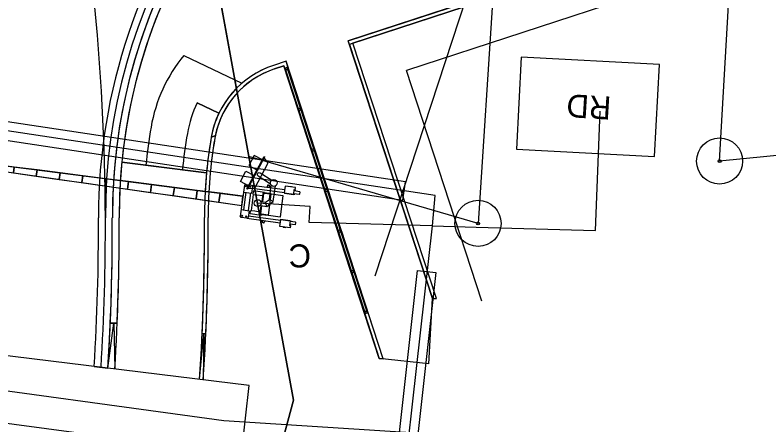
# Model space of a CAD drawing. Extents: x -728802 to -728097, y -1073200 to -1072700.
# Drawn here: x -728503.88 to -728487.53, y -1073043.74 to -1073034.86 of the extents above; entities that cross this region are included whole.
import ezdxf

# ---------------------------------------------------------------- set-up
doc = ezdxf.new("R2010")
doc.units = 0
for name, color, linetype in [('A5_JŽM', 7, 'Continuous'), ('Default', 7, 'Continuous'), ('Hranice parcel', 7, 'Continuous'), ('Projekt', 7, 'Continuous'), ('ZZZ_popisky', 7, 'Continuous')]:
    doc.layers.add(name, color=color, linetype=linetype)

# ---------------------------------------------------------------- blocks, each defined once
blk = doc.blocks.new('Závora C_2')
at = {"layer": 'Default'}
for p, q in [((-0.262, 0.267), (0.015, 1.015)), ((-0.033, 0.659), (0.235, 0.532)), ((-0.312, 0.367), (-0.338, 0.343)), ((-0.338, 0.343), (-0.338, -0.335)), ((-0.312, 0.367), (-0.189, 0.367)), ((-0.189, 0.367), (0.541, 0.367)), ((-0.189, 0.367), (-0.163, 0.343)), ((0.614, 0.452), (0.676, 0.452)), ((0.676, 0.452), (0.676, 0.445)), ((0.769, 0.395), (0.769, 0.367)), ((-0.338, 0.197), (-0.163, 0.197)), ((-0.288, 0.197), (-0.288, -0.188)), ((-0.187, 0.197), (-0.187, -0.188)), ((-0.163, 0.306), (0.541, 0.306)), ((-0.123, 0.174), (-0.123, -0.176)), ((0.259, 0.227), (0.259, -0.239)), ((-6.838, 0.058), (-0.338, 0.104)), ((-6.838, -0.049), (-6.838, 0.058)), ((-0.338, -0.096), (-0.338, 0.104)), ((-0.338, -0.096), (-0.338, 0.104)), ((-0.338, -0.096), (-0.338, 0.104)), ((-0.338, -0.096), (-0.338, 0.104)), ((0.202, -0.045), (0.165, 0.044)), ((0.329, 0.076), (0.239, 0.114)), ((-6.838, -0.049), (-0.338, -0.096)), ((-0.338, -0.188), (-0.163, -0.188)), ((-0.163, -0.188), (-0.163, -0.335)), ((-0.163, -0.298), (0.542, -0.298)), ((-0.312, -0.358), (-0.338, -0.335)), ((-0.189, -0.358), (-0.163, -0.335)), ((-0.189, -0.358), (0.542, -0.358)), ((0.614, -0.443), (0.676, -0.443)), ((0.676, -0.443), (0.676, -0.437)), ((0.769, -0.387), (0.769, -0.358))]:
    blk.add_line(p, q, dxfattribs=at)
for points in [[(-0.025, 0.945), (-0.214, 1.015), (-0.301, 0.78), (-0.112, 0.71)], [(-0.262, 0.267), (-0.274, 0.272), (0.003, 1.019), (0.015, 1.015)], [(-0.251, 0.296), (-0.129, 0.3), (-0.105, 0.313), (0.104, 0.877), (0.097, 0.901), (0.006, 0.989)], [(-0.066, 0.584), (-0.084, 0.597), (-0.089, 0.61), (-0.089, 0.625), (-0.087, 0.641), (-0.08, 0.65), (-0.07, 0.655), (-0.055, 0.66), (-0.043, 0.659), (-0.033, 0.659)], [(-0.247, 0.346), (-0.436, 0.416), (-0.349, 0.652), (-0.16, 0.582)], [(-0.066, 0.584), (0.218, 0.451)], [(-0.163, 0.343), (-0.163, 0.197)], [(0.066, 0.044), (0.165, 0.044), (0.239, 0.114), (0.239, 0.422)], [(0.071, -0.045), (0.202, -0.045), (0.329, 0.076), (0.329, 0.419)], [(0.179, 0.418), (0.166, 0.418), (0.165, 0.411), (0.16, 0.411), (0.16, 0.401), (0.157, 0.401), (0.157, 0.378), (0.148, 0.378), (0.148, 0.372), (0.148, 0.367)], [(0.179, 0.418), (0.192, 0.418), (0.193, 0.411), (0.197, 0.411), (0.197, 0.401), (0.201, 0.401), (0.201, 0.378), (0.21, 0.378), (0.21, 0.372), (0.21, 0.367)], [(0.542, 0.445), (0.542, 0.297), (0.747, 0.297), (0.747, 0.395), (0.769, 0.395), (0.769, 0.445), (0.542, 0.445)], [(0.614, 0.452), (0.614, 0.445)], [(0.655, 0.445), (0.614, 0.445)], [(0.872, 0.367), (0.747, 0.367)], [(0.872, 0.367), (0.872, 0.312), (0.866, 0.306), (0.747, 0.306)], [(0.116, 0.251), (-0.13, 0.251), (-0.13, 0.182), (-0.123, 0.174), (-0.04, 0.174), (-0.04, 0.177), (0.077, 0.177), (0.078, 0.181), (0.084, 0.181)], [(0.259, 0.238), (0.109, 0.238), (0.098, 0.236), (0.092, 0.23), (0.086, 0.223), (0.084, 0.219), (0.084, 0.045)], [(0.259, 0.238), (0.259, 0.227), (0.11, 0.227), (0.106, 0.225), (0.102, 0.222), (0.098, 0.218), (0.097, 0.213), (0.097, 0.045)], [(0.265, 0.238), (0.52, 0.238), (0.52, -0.239), (0.265, -0.239)], [(0.265, -0.239), (0.265, 0.238)], [(0.545, 0.297), (0.545, 0.289), (0.745, 0.289), (0.745, 0.297)], [(0.747, 0.297), (0.77, 0.297), (0.77, 0.306)], [(-6.338, -0.053), (-6.338, 0.061), (-6.838, 0.058), (-6.838, -0.049), (-6.338, -0.053)], [(-5.838, -0.057), (-5.838, 0.065), (-6.338, 0.061), (-6.338, -0.053), (-5.838, -0.057)], [(-5.338, -0.06), (-5.338, 0.068), (-5.838, 0.065), (-5.838, -0.057), (-5.338, -0.06)], [(-4.838, -0.064), (-4.838, 0.072), (-5.338, 0.068), (-5.338, -0.06), (-4.838, -0.064)], [(-4.338, -0.067), (-4.338, 0.076), (-4.838, 0.072), (-4.838, -0.064), (-4.338, -0.067)], [(-3.838, -0.071), (-3.838, 0.079), (-4.338, 0.076), (-4.338, -0.067), (-3.838, -0.071)], [(-3.338, -0.074), (-3.338, 0.083), (-3.838, 0.079), (-3.838, -0.071), (-3.338, -0.074)], [(-2.838, -0.078), (-2.838, 0.086), (-3.338, 0.083), (-3.338, -0.074), (-2.838, -0.078)], [(-2.338, -0.082), (-2.338, 0.09), (-2.838, 0.086), (-2.838, -0.078), (-2.338, -0.082)], [(-1.838, -0.085), (-1.838, 0.093), (-2.338, 0.09), (-2.338, -0.082), (-1.838, -0.085)], [(-1.338, -0.089), (-1.338, 0.097), (-1.838, 0.093), (-1.838, -0.085), (-1.338, -0.089)], [(-0.838, -0.092), (-0.838, 0.101), (-1.338, 0.097), (-1.338, -0.089), (-0.838, -0.092)], [(-0.338, -0.096), (-0.338, 0.104), (-0.838, 0.101), (-0.838, -0.092), (-0.338, -0.096)], [(0.259, -0.239), (0.109, -0.239), (0.098, -0.237), (0.092, -0.231), (0.086, -0.224), (0.084, -0.22), (0.084, -0.044)], [(0.259, -0.228), (0.11, -0.228), (0.106, -0.226), (0.102, -0.223), (0.098, -0.219), (0.097, -0.214), (0.097, -0.044)], [(0.116, -0.253), (-0.13, -0.253), (-0.13, -0.184), (-0.123, -0.176), (-0.04, -0.176), (-0.04, -0.178), (0.077, -0.178), (0.078, -0.182), (0.084, -0.182)], [(0.542, -0.437), (0.542, -0.288), (0.747, -0.288), (0.747, -0.387), (0.769, -0.387), (0.769, -0.437), (0.542, -0.437)], [(0.545, -0.288), (0.545, -0.281), (0.745, -0.281), (0.745, -0.288)], [(0.747, -0.288), (0.77, -0.288), (0.77, -0.298)], [(0.872, -0.358), (0.872, -0.304), (0.866, -0.298), (0.747, -0.298)], [(-0.189, -0.358), (-0.312, -0.358)], [(0.179, -0.409), (0.166, -0.409), (0.165, -0.403), (0.16, -0.403), (0.16, -0.393), (0.157, -0.393), (0.157, -0.37), (0.148, -0.37), (0.148, -0.364), (0.148, -0.358)], [(0.179, -0.409), (0.192, -0.409), (0.193, -0.403), (0.197, -0.403), (0.197, -0.393), (0.201, -0.393), (0.201, -0.37), (0.21, -0.37), (0.21, -0.364), (0.21, -0.358)], [(0.655, -0.437), (0.614, -0.437)], [(0.614, -0.443), (0.614, -0.437)], [(0.872, -0.358), (0.747, -0.358)]]:
    blk.add_lwpolyline(points, dxfattribs=at)
for centre, radius in [((0.286, 0.479), 0.0735), ((-0.296, 0.327), 0.0119), ((-0.212, 0.328), 0.0119), ((0, 0), 0.0742), ((-0.296, -0.319), 0.0119), ((-0.212, -0.32), 0.0119)]:
    blk.add_circle(centre, radius, dxfattribs=at)

msp = doc.modelspace()

# ---------------------------------------------------------------- linework, layer by layer
at = {"layer": 'A5_JŽM'}
for points in [[(-728320.8, -1073026.914), (-728374.008, -1073033.722), (-728429.095, -1073040.747), (-728461.932, -1073044.273), (-728481.199, -1073044.815), (-728499.353, -1073043.648), (-728506.01, -1073042.737), (-728514.574, -1073041.329), (-728535.848, -1073035.998), (-728561.353, -1073026.113), (-728583.963, -1073013.524), (-728603.757, -1072998.891), (-728619.185, -1072984.418), (-728634.193, -1072966.825), (-728646.078, -1072949.194), (-728656.182, -1072930.072), (-728664.987, -1072910.227), (-728668.627, -1072901.808), (-728681.252, -1072876.016), (-728691.886, -1072859.663)], [(-728498.81, -1073037.92), (-728499.78, -1073032.61), (-728497.54, -1073030.15), (-728493.68, -1073027.94), (-728443.97, -1073014.59), (-728443.68, -1073014.51), (-728441.09, -1073023.23), (-728428.92, -1073019.94), (-728429.82, -1073016.43), (-728427.49, -1073015.84), (-728421.24, -1073014.23), (-728422.34, -1073010.27), (-728422.77, -1073008.34), (-728418.21, -1073007), (-728380.57, -1072997.2), (-728343.1, -1072987.57), (-728330.49, -1072984.52), (-728326.79, -1072988.95)], [(-728327.13, -1073038.08), (-728361.73, -1073039.5), (-728434.43, -1073049.27), (-728470.97, -1073054.08), (-728490.19, -1073055.04), (-728500.77, -1073053.31), (-728499.61, -1073049.44), (-728498.79, -1073046.71), (-728497.84, -1073043.2), (-728498.81, -1073037.92)], [(-728514.104, -1073040.67), (-728514.376, -1073042.064), (-728513.93, -1073042.165), (-728506.122, -1073043.424), (-728499.477, -1073044.316), (-728498.964, -1073044.302), (-728498.807, -1073042.881), (-728505.883, -1073042.015), (-728513.61, -1073040.728), (-728514.104, -1073040.67)]]:
    msp.add_lwpolyline(points, dxfattribs=at)
at = {"layer": 'Hranice parcel'}
for p in [(-728499.78, -1073032.61), (-728493.84, -1073039.37)]:
    msp.add_line(p, (-728498.81, -1073037.92), dxfattribs=at)
for points in [[(-728428.94, -1073031.04), (-728435.33, -1073031.82), (-728462.29, -1073035.43), (-728488.6, -1073038.02), (-728488.39, -1073034.38), (-728493.51, -1073034.35), (-728493.84, -1073039.37)], [(-728498.81, -1073037.92), (-728497.84, -1073043.2), (-728498.79, -1073046.71)]]:
    msp.add_lwpolyline(points, dxfattribs=at)
for centre, radius in [((-728488.6, -1073038.02), 0.5), ((-728488.6, -1073038.02), 0.0303), ((-728493.84, -1073039.37), 0.5), ((-728493.84, -1073039.37), 0.0303)]:
    msp.add_circle(centre, radius, dxfattribs=at)
at = {"layer": 'Projekt'}
for p, q in [((-728494.83, -1073040.995), (-728496.655, -1073035.417)), ((-728494.744, -1073041), (-728496.554, -1073035.468)), ((-728500.219, -1073035.729), (-728498.963, -1073036.334)), ((-728498.004, -1073035.858), (-728498.279, -1073035.948)), ((-728497.963, -1073035.984), (-728498.004, -1073035.858)), ((-728495.895, -1073042.308), (-728498.004, -1073035.858)), ((-728498.254, -1073036.024), (-728498.056, -1073035.959)), ((-728498.056, -1073035.959), (-728498.04, -1073036.008)), ((-728495.982, -1073042.298), (-728498.056, -1073035.959)), ((-728498.04, -1073036.008), (-728497.963, -1073035.984)), ((-728496.292, -1073041.302), (-728498.017, -1073036.027)), ((-728497.948, -1073036.031), (-728497.98, -1073036.041)), ((-728496.244, -1073041.287), (-728497.97, -1073036.012)), ((-728497.676, -1073036.863), (-728497.948, -1073036.031)), ((-728497.98, -1073036.041), (-728498.024, -1073036.056)), ((-728498.024, -1073036.056), (-728497.752, -1073036.888)), ((-728493.757, -1073041.058), (-728495.393, -1073036.056)), ((-728499.933, -1073036.755), (-728499.46, -1073036.982)), ((-728497.752, -1073036.888), (-728497.676, -1073036.863)), ((-728497.66, -1073036.91), (-728497.736, -1073036.935)), ((-728497.736, -1073036.935), (-728497.464, -1073037.767)), ((-728497.388, -1073037.742), (-728497.66, -1073036.91)), ((-728499.627, -1073037.501), (-728499.54, -1073037.473)), ((-728499.54, -1073037.473), (-728499.627, -1073037.501)), ((-728497.464, -1073037.767), (-728497.388, -1073037.742)), ((-728497.373, -1073037.789), (-728497.449, -1073037.814)), ((-728497.449, -1073037.814), (-728497.177, -1073038.646)), ((-728497.101, -1073038.621), (-728497.373, -1073037.789)), ((-728501.566, -1073038.044), (-728499.73, -1073038.278)), ((-728501.599, -1073038.443), (-728499.759, -1073038.678)), ((-728501.599, -1073038.443), (-728499.759, -1073038.678)), ((-728497.177, -1073038.646), (-728497.132, -1073038.631)), ((-728497.132, -1073038.631), (-728497.101, -1073038.621)), ((-728497.124, -1073038.681), (-728497.161, -1073038.693)), ((-728497.161, -1073038.693), (-728496.889, -1073039.525)), ((-728497.085, -1073038.668), (-728497.124, -1073038.681)), ((-728496.813, -1073039.5), (-728497.085, -1073038.668)), ((-728499.773, -1073039.242), (-728499.773, -1073039.242)), ((-728496.889, -1073039.525), (-728496.813, -1073039.5)), ((-728496.798, -1073039.548), (-728496.874, -1073039.573)), ((-728496.874, -1073039.573), (-728496.602, -1073040.404)), ((-728496.525, -1073040.379), (-728496.798, -1073039.548)), ((-728496.602, -1073040.404), (-728496.525, -1073040.379)), ((-728496.51, -1073040.427), (-728496.586, -1073040.452)), ((-728496.238, -1073041.258), (-728496.51, -1073040.427)), ((-728496.586, -1073040.452), (-728496.314, -1073041.283)), ((-728494.91, -1073042.414), (-728494.83, -1073040.995)), ((-728496.314, -1073041.283), (-728496.238, -1073041.258)), ((-728496.222, -1073041.306), (-728496.298, -1073041.331)), ((-728496.298, -1073041.331), (-728495.982, -1073042.298)), ((-728495.895, -1073042.308), (-728496.222, -1073041.306)), ((-728501.868, -1073042.506), (-728501.742, -1073041.53)), ((-728501.817, -1073041.53), (-728501.667, -1073041.53)), ((-728501.742, -1073041.53), (-728501.718, -1073042.525)), ((-728499.825, -1073041.757), (-728499.785, -1073041.759)), ((-728499.745, -1073041.761), (-728499.825, -1073041.757)), ((-728499.879, -1073042.75), (-728499.785, -1073041.759)), ((-728499.785, -1073041.759), (-728499.799, -1073042.76)), ((-728499.785, -1073041.759), (-728499.745, -1073041.761)), ((-728495.982, -1073042.298), (-728495.895, -1073042.308)), ((-728494.91, -1073042.414), (-728495.982, -1073042.298))]:
    msp.add_line(p, q, dxfattribs=at)
for points in [[(-728488.131, -1073032.628), (-728496.655, -1073035.417)], [(-728488.106, -1073032.704), (-728496.63, -1073035.493)], [(-728496.655, -1073035.417), (-728491.352, -1073033.682), (-728490.59, -1073033.433), (-728489.062, -1073032.933), (-728488.985, -1073032.908), (-728488.606, -1073032.784), (-728488.594, -1073032.822), (-728488.581, -1073032.86), (-728496.554, -1073035.468), (-728496.63, -1073035.493), (-728496.655, -1073035.417), (-728496.655, -1073035.417)], [(-728487.82, -1073033.579), (-728495.393, -1073036.056)], [(-728494.83, -1073040.995), (-728494.744, -1073041), (-728496.554, -1073035.468), (-728496.63, -1073035.493), (-728494.83, -1073040.995), (-728494.83, -1073040.995)], [(-728495.471, -1073038.866), (-728495.411, -1073038.47), (-728513.167, -1073035.794), (-728513.227, -1073036.19), (-728495.471, -1073038.866)], [(-728498.004, -1073035.858), (-728498.279, -1073035.948)], [(-728494.829, -1073039.422), (-728494.767, -1073038.764), (-728513.916, -1073035.879)], [(-728498.056, -1073035.959), (-728498.254, -1073036.024)], [(-728499.46, -1073036.982), (-728499.933, -1073036.755)], [(-728494.829, -1073039.422), (-728493.88, -1073039.45), (-728491.292, -1073039.525), (-728491.192, -1073036.939)], [(-728499.73, -1073038.278), (-728500.251, -1073038.212), (-728501.045, -1073038.11), (-728501.566, -1073038.044)], [(-728500.251, -1073038.212), (-728499.73, -1073038.278), (-728499.73, -1073038.278)], [(-728494.829, -1073039.423), (-728497.506, -1073039.348), (-728497.482, -1073039.008), (-728498.619, -1073038.931)], [(-728499.688, -1073048.436), (-728495.793, -1073047.995), (-728494.829, -1073039.422)], [(-728495.526, -1073047.393), (-728495.924, -1073047.349), (-728495.151, -1073040.392), (-728494.753, -1073040.436), (-728495.526, -1073047.393)], [(-728501.667, -1073041.53), (-728501.742, -1073041.53), (-728501.817, -1073041.53)], [(-728501.868, -1073042.506), (-728502.166, -1073042.47)], [(-728502.166, -1073042.47), (-728501.868, -1073042.506)]]:
    msp.add_lwpolyline(points, dxfattribs=at)
msp.add_lwpolyline([(-728489.907, -1073035.925), (-728492.903, -1073035.767), (-728493.008, -1073037.764), (-728490.012, -1073037.922)], close=True, dxfattribs=at)
for centre in [(-728497.994, -1073036.02), (-728497.706, -1073036.899), (-728497.419, -1073037.778), (-728497.131, -1073038.657), (-728496.843, -1073039.536), (-728496.556, -1073040.415), (-728496.268, -1073041.295)]:
    msp.add_circle(centre, 0.025, dxfattribs=at)
for centre, radius, start, end in [((-728489.773, -1073039.206), 12.3, 105.42, 180.2086), ((-728489.773, -1073039.206), 12.3, 105.42, 180.2086), ((-728489.773, -1073039.206), 12, 105.42, 180.2086), ((-728489.773, -1073039.206), 11.85, 105.42, 180.2086), ((-728489.773, -1073039.206), 12.15, 116.9619, 180.2086), ((-728489.773, -1073039.206), 12, 121.8734, 180.2086), ((-728489.773, -1073039.206), 12, 121.8734, 180.2086), ((-728489.773, -1073039.206), 11.85, 121.8734, 180.2086), ((-728551.773, -1073039.431), 49.85, 0.2087, 11.4145), ((-728497.657, -1073037.849), 3.325, 140.3957, 170.238), ((-728497.657, -1073037.849), 2, 108.1145, 170.238), ((-728497.657, -1073037.849), 2, 108.1145, 169.9746), ((-728497.657, -1073037.849), 1.92, 108.1145, 170.238), ((-728497.657, -1073037.849), 1.92, 108.1145, 168.6899), ((-728497.657, -1073037.849), 2.525, 154.3177, 170.238), ((-728497.657, -1073037.849), 2.525, 154.3177, 170.238), ((-728497.657, -1073037.849), 2, 154.3177, 170.238), ((-728489.773, -1073039.206), 11.325, 170.238, 174.45), ((-728489.773, -1073039.206), 10.525, 170.238, 174.5817), ((-728489.773, -1073039.206), 10.525, 170.238, 174.5817), ((-728497.657, -1073037.849), 2, 169.9746, 170.238), ((-728497.657, -1073037.849), 1.92, 168.6899, 170.238), ((-728489.773, -1073039.206), 10, 170.238, 180.2086), ((-728489.773, -1073039.206), 10, 170.238, 180.2086), ((-728489.773, -1073039.206), 10, 170.238, 174.6795), ((-728489.773, -1073039.206), 9.92, 170.238, 180.2086), ((-728489.773, -1073039.206), 9.92, 170.2672, 180.2086), ((-728489.777, -1073039.205), 9.917, 170.238, 170.2672), ((-728489.773, -1073039.206), 11.85, 174.3733, 176.3095), ((-728489.773, -1073039.206), 10, 174.6795, 176.9749), ((-728551.773, -1073039.431), 49.7, 356.4947, 0.2086), ((-728551.773, -1073039.431), 49.7, 356.4947, 0.2086), ((-728551.773, -1073039.431), 49.85, 356.4843, 0.2086), ((-728551.773, -1073039.431), 50, 356.4739, 0.2086), ((-728551.773, -1073039.431), 50, 357.5948, 0.2086), ((-728551.773, -1073039.431), 50, 357.5948, 0.2086), ((-728551.773, -1073039.431), 50.15, 356.4635, 0.2086), ((-728551.773, -1073039.431), 50.15, 357.602, 0.2086), ((-728551.773, -1073039.431), 52, 356.341, 0.2086), ((-728551.773, -1073039.431), 52.08, 356.3359, 0.2086), ((-728551.773, -1073039.431), 52, 359.9296, 0.2086), ((-728551.773, -1073039.431), 52.08, 359.9585, 0.2086), ((-728551.773, -1073039.431), 52.08, 359.9006, 359.9585), ((-728551.773, -1073039.431), 52, 358.8534, 359.8716), ((-728551.772, -1073039.431), 52, 359.8716, 359.9296), ((-728551.773, -1073039.431), 52.08, 358.8842, 359.9006), ((-728551.773, -1073039.431), 52.08, 358.8259, 358.8842), ((-728551.773, -1073039.431), 52, 357.7701, 358.795), ((-728551.773, -1073039.431), 52, 358.795, 358.8534), ((-728551.773, -1073039.431), 52.08, 357.8028, 358.8259), ((-728551.773, -1073039.431), 52.08, 357.7441, 357.8028), ((-728551.773, -1073039.431), 50, 356.4739, 357.5948), ((-728551.773, -1073039.431), 52, 357.436, 357.7114), ((-728551.773, -1073039.431), 52, 357.7114, 357.7701), ((-728551.773, -1073039.431), 52.08, 357.436, 357.7441)]:
    msp.add_arc(centre, radius, start, end, dxfattribs=at)
at = {"layer": 'ZZZ_popisky'}
msp.add_lwpolyline([(-728496.069, -1073040.506), (-728413.218, -1072787.634), (-728463.108, -1072771.288)], dxfattribs=at)

# ---------------------------------------------------------------- block references
at = {"layer": 'Projekt', "rotation": -7.690384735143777}
msp.add_blockref('Závora C_2', (-728498.619, -1073038.931), dxfattribs=at)

# ---------------------------------------------------------------- texts
at = {"layer": 'Projekt'}
for s, rotation, p in [('RD', 176.5903, (-728490.939, -1073036.625)), ('C', 180, (-728497.464, -1073039.825))]:
    msp.add_text(s, height=0.5, rotation=rotation, dxfattribs=at).set_placement(p)

doc.saveas('drawing.dxf')
